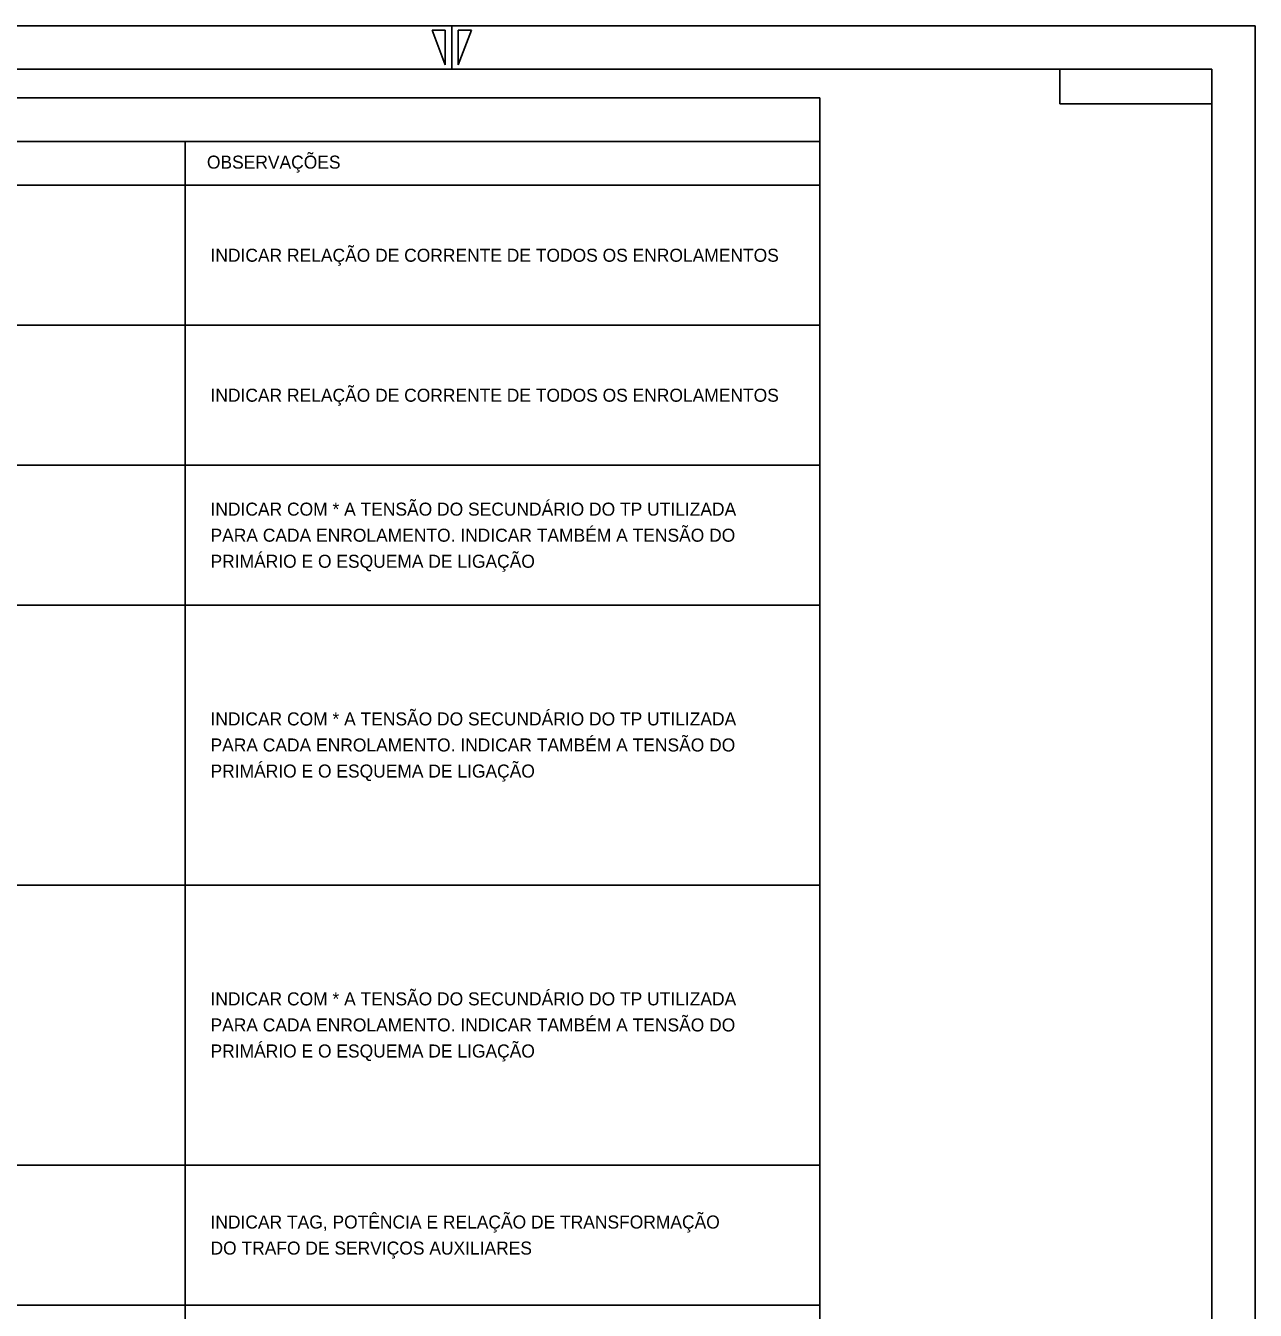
# Model space of a CAD drawing. Extents: x 563 to 3226, y 358 to 960.
# Drawn here: x 2031.8 to 2314.9, y 656.2 to 952 of the extents above; entities that cross this region are included whole.
import ezdxf

# ---------------------------------------------------------------- set-up
doc = ezdxf.new("R2010")
doc.units = 0
doc.layers.add('Default', color=7, linetype='Continuous')
doc.layers.add('New Level (0)', color=7, linetype='Continuous')

msp = doc.modelspace()

# ---------------------------------------------------------------- linework, layer by layer
at = {"layer": 'New Level (0)'}
for p, q in [((2314.88, 951.96), (1473.88, 951.96)), ((2314.88, 951.96), (1473.88, 951.96)), ((2128.38, 950.96), (2125.38, 950.96)), ((2125.38, 950.96), (2128.38, 942.96)), ((2128.38, 942.96), (2128.38, 950.96)), ((2129.88, 951.96), (2129.88, 941.96)), ((2131.38, 942.96), (2131.38, 950.96)), ((2131.38, 950.96), (2134.38, 950.96)), ((2134.38, 950.96), (2131.38, 942.96)), ((2314.88, 357.96), (2314.88, 951.96)), ((2314.88, 357.96), (2314.88, 951.96)), ((2304.88, 941.96), (1483.88, 941.96)), ((2269.88, 933.96), (2269.88, 941.96)), ((2304.88, 367.96), (2304.88, 941.96)), ((2304.88, 367.96), (2304.88, 941.96)), ((1514.44, 935.35), (2214.61, 935.35)), ((2214.61, 915.21), (2214.61, 935.35)), ((2304.88, 933.96), (2269.88, 933.96)), ((1864.53, 925.28), (2214.61, 925.28)), ((2068.49, 915.21), (2068.49, 925.28)), ((1514.44, 882.98), (2214.61, 882.98)), ((1514.44, 850.75), (2214.61, 850.75)), ((1514.44, 818.53), (2214.61, 818.53)), ((1514.44, 754.07), (2214.61, 754.07)), ((1514.44, 689.61), (2214.61, 689.61)), ((1514.44, 657.39), (2214.61, 657.39))]:
    msp.add_line(p, q, dxfattribs=at)
for points in [[(1864.53, 915.21), (2068.49, 915.21), (2068.49, 429.83), (1864.53, 429.83)], [(2068.49, 915.21), (2214.61, 915.21), (2214.61, 429.83), (2068.49, 429.83)]]:
    msp.add_lwpolyline(points, close=True, dxfattribs=at)

# ---------------------------------------------------------------- texts
at = {"layer": 'Default'}
for s, p in [('OBSERVAÇÕES', (2073.5, 919.04)), ('INDICAR RELAÇÃO DE CORRENTE DE TODOS OS ENROLAMENTOS', (2074.33, 897.6)), ('INDICAR RELAÇÃO DE CORRENTE DE TODOS OS ENROLAMENTOS', (2074.33, 865.37)), ('INDICAR COM * A TENSÃO DO SECUNDÁRIO DO TP UTILIZADA ', (2074.33, 839.14)), ('PARA CADA ENROLAMENTO. INDICAR TAMBÉM A TENSÃO DO ', (2074.33, 833.14)), ('PRIMÁRIO E O ESQUEMA DE LIGAÇÃO', (2074.33, 827.14)), ('INDICAR COM * A TENSÃO DO SECUNDÁRIO DO TP UTILIZADA ', (2074.33, 790.84)), ('PARA CADA ENROLAMENTO. INDICAR TAMBÉM A TENSÃO DO ', (2074.33, 784.84)), ('PRIMÁRIO E O ESQUEMA DE LIGAÇÃO', (2074.33, 778.84)), ('INDICAR COM * A TENSÃO DO SECUNDÁRIO DO TP UTILIZADA ', (2074.33, 726.38)), ('PARA CADA ENROLAMENTO. INDICAR TAMBÉM A TENSÃO DO ', (2074.33, 720.38)), ('PRIMÁRIO E O ESQUEMA DE LIGAÇÃO', (2074.33, 714.38)), ('INDICAR TAG, POTÊNCIA E RELAÇÃO DE TRANSFORMAÇÃO', (2074.33, 675)), ('DO TRAFO DE SERVIÇOS AUXILIARES', (2074.33, 669))]:
    msp.add_text(s, height=3, dxfattribs=at).set_placement(p)

doc.saveas('drawing.dxf')
